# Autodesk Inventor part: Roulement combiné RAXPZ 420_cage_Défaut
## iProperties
Shininess: 64.0
Length Units: 11269
Angle Units: 11279
Time Units: 11290
Mass Units: 11283
Length Display Precision: 3
Angle Display Precision: 2
Compacted: True
Part Number: Roulement combiné RAXPZ 420_cage_Défaut
Document SubType Name: Modeling
Created: 2006-01
Material: Par défaut
Designer: riri
Density: 0.0
Volumn: 0.0
Area: 0.0
PropertySet Name: Model Information
Control State: 0
Master: False
Checked Out: False
Author: riri
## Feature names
1. Base1
